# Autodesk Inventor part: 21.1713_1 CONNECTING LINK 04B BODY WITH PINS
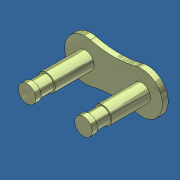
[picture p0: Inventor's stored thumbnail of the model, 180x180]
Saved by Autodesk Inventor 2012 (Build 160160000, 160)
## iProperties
Created: 2016-02
Part Number: 21.1713_1 CONNECTING LINK 04B BODY WITH PINS
Material: Steel
Document SubType Name: Modeling
Designer: Admin
Density: 7.85 g/cm^3
Mass: 0.455679 g
Surface Area: 1.7286 cm^2
Volume: 0.0580482 cm^3
Author: Admin
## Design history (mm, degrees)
feature "Base1"
sketch "Sketch1"
  geometry: C1 r 0.788 at (2.997, -11.471) reference; C2 r 0.788 at (-2.997, -11.471) reference; A1 r 9.654 centre (0, 0) between (-2.441, -9.341) and (2.441, -9.341) reference; A2 r 2.202 centre (-2.997, -11.471) between (-2.441, -9.341) and (-2.441, -13.601) reference; A3 r 9.654 centre (0, -22.942) between (2.441, -13.601) and (-2.441, -13.601) reference; A4 r 2.202 centre (2.997, -11.471) between (2.441, -13.601) and (2.441, -9.341) reference; 1 further point
extrude "Extrusion1" cut sketch "Sketch1" stored distance "d0" = 25.4; taper "d1" = 0 deg
body "Solid1"
